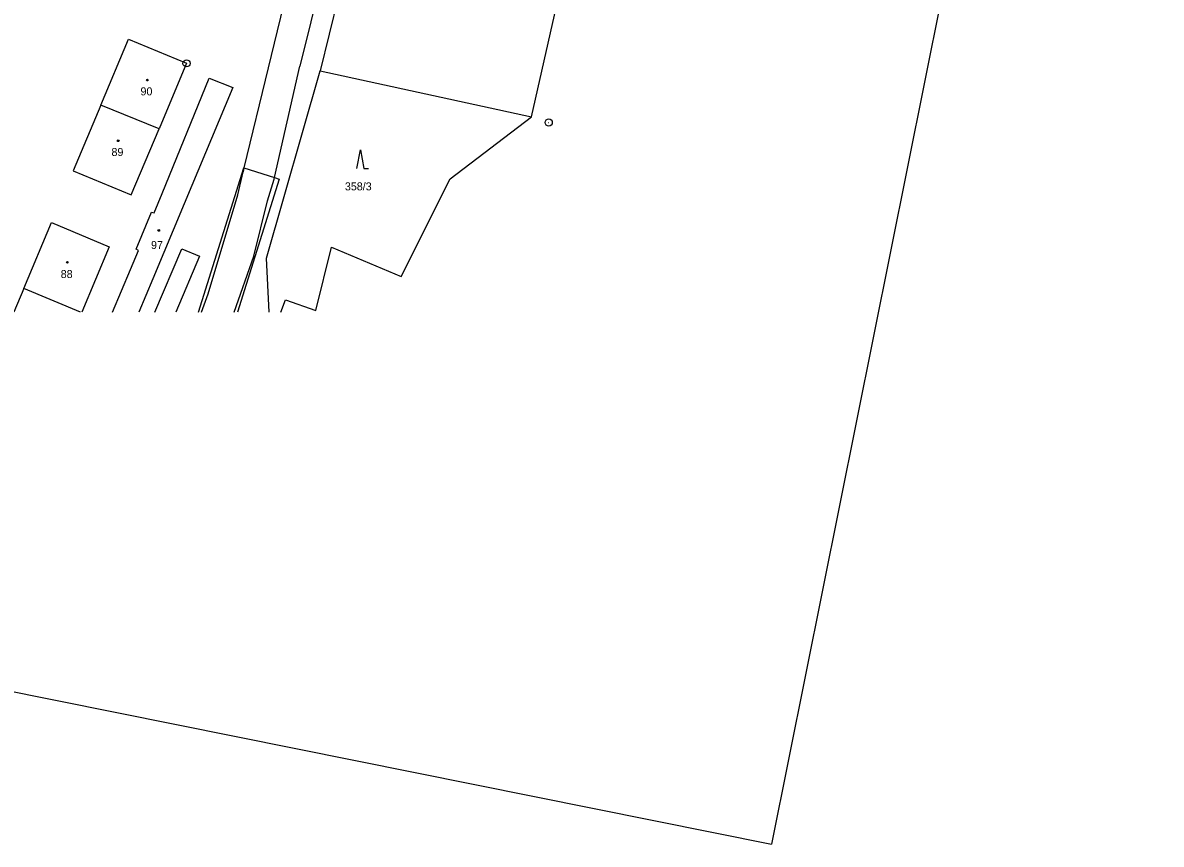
# Model space of a CAD drawing. Extents: x -778045 to -777594, y -1202682 to -1202213.
# Drawn here: x -777835.6 to -777593.8, y -1202682.1 to -1202507.7 of the extents above; entities that cross this region are included whole.
import ezdxf

# ---------------------------------------------------------------- set-up
doc = ezdxf.new("R2010")
doc.units = 0
for name, color, linetype in [('Katastr_Hranice parcel', 7, 'Continuous'), ('Katastr_Parcelní čísla', 7, 'Continuous'), ('Katastr_Slučkované čáry', 7, 'Continuous'), ('Katastr_Značky kultur', 7, 'Continuous')]:
    doc.layers.add(name, color=color, linetype=linetype)

msp = doc.modelspace()

# ---------------------------------------------------------------- linework, layer by layer
at = {"layer": 'Defpoints'}
for p in [(-777593.79, -1202270.29), (-777959.92, -1202625.08)]:
    msp.add_line(p, (-777676.59, -1202682.05), dxfattribs=at)
at = {"layer": 'Katastr_Hranice parcel'}
msp.add_line((-777750.49, -1202426.97), (-777772.39, -1202517.89), dxfattribs=at)
for points in [[(-777746.67, -1202395.6), (-777776.75, -1202516.88)], [(-777727.56, -1202527.62), (-777701.15, -1202410.88)], [(-777775.07, -1202482.53), (-777783.45, -1202517.26)], [(-777819, -1202525.15), (-777813.09, -1202511.12)], [(-777813.09, -1202511.12), (-777800.79, -1202516.27)], [(-777800.79, -1202516.27), (-777806.63, -1202530.18)], [(-777783.45, -1202517.26), (-777788.63, -1202538.49)], [(-777782.12, -1202540.54), (-777776.75, -1202516.88)], [(-777805.98, -1202543.9), (-777796.02, -1202519.44)], [(-777796.02, -1202519.44), (-777790.99, -1202521.38)], [(-777783.8, -1202557.62), (-777772.39, -1202517.89)], [(-777772.39, -1202517.89), (-777727.56, -1202527.62)], [(-777790.99, -1202521.38), (-777801.3, -1202546.1)], [(-777819, -1202525.15), (-777824.88, -1202539.11)], [(-777806.63, -1202530.18), (-777819, -1202525.15)], [(-777744.79, -1202540.77), (-777727.56, -1202527.62)], [(-777812.54, -1202544.23), (-777806.63, -1202530.18)], [(-777824.88, -1202539.11), (-777812.54, -1202544.23)], [(-777789.91, -1202544.2), (-777788.76, -1202539.31)], [(-777788.63, -1202538.49), (-777788.76, -1202539.31)], [(-777783.58, -1202545.49), (-777782.19, -1202540.84)], [(-777782.19, -1202540.84), (-777782.12, -1202540.54)], [(-777755.21, -1202561.5), (-777744.79, -1202540.77)], [(-777807.7, -1202548.04), (-777805.98, -1202543.9)], [(-777796.18, -1202565.22), (-777789.91, -1202544.2)], [(-777801.3, -1202546.1), (-777807.95, -1202562.04)], [(-777786.51, -1202557.2), (-777783.58, -1202545.49)], [(-777811.52, -1202555.73), (-777808.24, -1202547.86)], [(-777808.24, -1202547.86), (-777807.7, -1202548.04)], [(-777835.36, -1202564.07), (-777829.49, -1202550.08)], [(-777829.49, -1202550.08), (-777817.22, -1202555.24)], [(-777817.22, -1202555.24), (-777823.04, -1202569.12)], [(-777812.73, -1202560.08), (-777811.02, -1202555.98)], [(-777811.02, -1202555.98), (-777811.52, -1202555.73)], [(-777773.36, -1202568.73), (-777770.03, -1202555.33)], [(-777770.03, -1202555.33), (-777755.21, -1202561.5)], [(-777790.68, -1202569.12), (-777786.51, -1202557.2)], [(-777783.28, -1202569.12), (-777783.8, -1202557.62)], [(-777816.51, -1202569.12), (-777812.73, -1202560.08)], [(-777807.95, -1202562.04), (-777810.9, -1202569.12)], [(-777835.36, -1202564.07), (-777837.48, -1202569.12)], [(-777823.29, -1202569.12), (-777835.36, -1202564.07)], [(-777797.59, -1202569.12), (-777796.18, -1202565.22)], [(-777780.76, -1202569.12), (-777779.79, -1202566.51)], [(-777779.79, -1202566.51), (-777773.36, -1202568.73)]]:
    msp.add_lwpolyline(points, dxfattribs=at)
at = {"layer": 'Katastr_Slučkované čáry'}
for points in [[(-777798.24, -1202569.12), (-777788.63, -1202538.49)], [(-777788.63, -1202538.49), (-777782.12, -1202540.54)], [(-777781.1, -1202540.86), (-777789.98, -1202569.12)], [(-777782.12, -1202540.54), (-777781.1, -1202540.86)], [(-777807.52, -1202569.12), (-777801.8, -1202555.63)], [(-777801.8, -1202555.63), (-777798.04, -1202557.23)], [(-777798.04, -1202557.23), (-777803.1, -1202569.12)]]:
    msp.add_lwpolyline(points, dxfattribs=at)
at = {"layer": 'Katastr_Značky kultur'}
for p, q in [((-777800.85, -1202516.28), (-777800.75, -1202516.28)), ((-777723.92, -1202528.84), (-777723.82, -1202528.84))]:
    msp.add_line(p, q, dxfattribs=at)
msp.add_lwpolyline([(-777764.62, -1202538.61), (-777763.87, -1202534.61), (-777763.12, -1202538.61), (-777762.12, -1202538.61)], dxfattribs=at)
for centre, radius in [((-777800.8, -1202516.28), 0.756), ((-777809.11, -1202519.85), 0.175), ((-777723.87, -1202528.84), 0.756), ((-777815.31, -1202532.72), 0.175), ((-777806.69, -1202551.76), 0.175), ((-777826.1, -1202558.51), 0.175)]:
    msp.add_circle(centre, radius, dxfattribs=at)

# ---------------------------------------------------------------- texts
at = {"layer": 'Katastr_Parcelní čísla'}
for s, p in [('90', (-777810.58, -1202523.08)), ('89', (-777816.74, -1202535.96)), ('358/3', (-777767.17, -1202543.25)), ('97', (-777808.34, -1202555.7)), ('88', (-777827.52, -1202561.86))]:
    msp.add_text(s, height=1.7, dxfattribs=at).set_placement(p)

doc.saveas('drawing.dxf')
